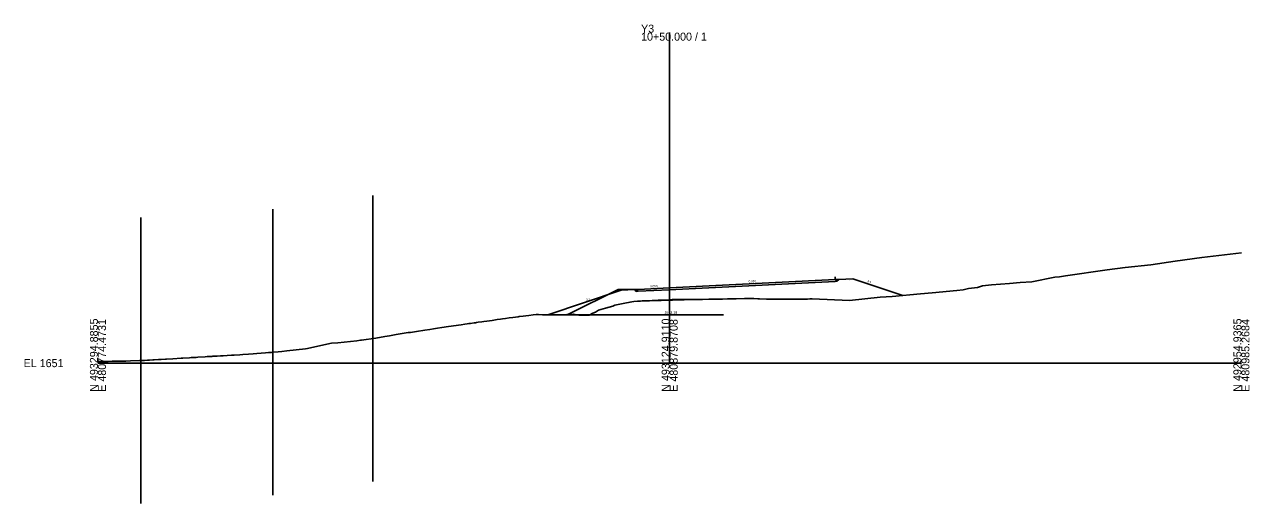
# Model space of a CAD drawing. Extents: x -26 to 481018, y -48 to 493233.
# Drawn here: x -25.7 to 402.8, y 450.9 to 618.4 of the extents above; entities that cross this region are included whole.
import ezdxf

# ---------------------------------------------------------------- set-up
doc = ezdxf.new("R2010")
doc.units = 0
for name, color, linetype in [('Exist Cross Section Cell', 7, 'Continuous'), ('Exist XS Center Line Elevation Label', 7, 'Continuous'), ('Exist XS Ground Line', 7, 'Continuous'), ('Prop XS Dump Level', 7, 'Continuous'), ('Prop XS Earthwork Shape', 7, 'Continuous'), ('Prop XS EOT Tick Mark', 7, 'Continuous'), ('Prop XS Finish Grade', 7, 'Continuous'), ('Prop XS Finish Grade Earthwork', 7, 'Continuous'), ('Prop XS Finish Grade Pavement', 7, 'Continuous'), ('Prop XS Pvmt Edge Slope', 7, 'Continuous'), ('Prop XS SE Text', 7, 'Continuous'), ('Prop XS Shoulder Borrow Shape', 7, 'Continuous'), ('Prop XS Side Slope Text', 7, 'Continuous'), ('Prop XS Subgrade Earthwork', 7, 'Continuous'), ('Scratch_Level_2', 7, 'Continuous'), ('Scratch_Level_4', 7, 'Continuous'), ('Scratch_Level_5', 7, 'Continuous')]:
    doc.layers.add(name, color=color, linetype=linetype)

msp = doc.modelspace()

# ---------------------------------------------------------------- linework, layer by layer
at = {"layer": 'Exist Cross Section Cell'}
for p, q in [((200, 500), (200, 615.55)), ((0, 500), (200, 500)), ((200, 500), (400, 500))]:
    msp.add_line(p, q, dxfattribs=at)
at = {"layer": 'Exist XS Ground Line'}
for p, q in [((376.79, 535.62), (386.19, 536.91)), ((386.19, 536.91), (400, 538.52)), ((338.48, 530.56), (353.09, 532.59)), ((353.09, 532.59), (359.3, 533.49)), ((359.3, 533.49), (368.34, 534.34)), ((368.34, 534.34), (376.79, 535.62)), ((309.46, 527.08), (312.54, 527.4)), ((312.54, 527.4), (318.83, 527.9)), ((318.83, 527.9), (322.57, 528.16)), ((322.57, 528.16), (326.64, 528.41)), ((326.64, 528.41), (334.78, 530.01)), ((334.78, 530.01), (336.43, 530.19)), ((336.43, 530.19), (338.48, 530.56)), ((262.92, 521.94), (273.67, 523.04)), ((273.67, 523.04), (277.85, 523.36)), ((277.85, 523.36), (287.78, 524.27)), ((287.78, 524.27), (291.83, 524.6)), ((291.83, 524.6), (300.49, 525.41)), ((300.49, 525.41), (302.66, 525.69)), ((302.66, 525.69), (304.51, 526.1)), ((304.51, 526.1), (307.67, 526.5)), ((307.67, 526.5), (309.46, 527.08)), ((174.04, 517.87), (175.15, 518.58)), ((175.15, 518.58), (177.51, 519.18)), ((177.51, 519.18), (180.09, 519.96)), ((180.09, 519.96), (180.83, 520.23)), ((180.83, 520.23), (184.3, 520.95)), ((184.3, 520.95), (186.14, 521.34)), ((186.14, 521.34), (186.75, 521.42)), ((186.75, 521.42), (187.5, 521.52)), ((187.5, 521.52), (188.8, 521.63)), ((188.8, 521.63), (189.83, 521.71)), ((189.83, 521.71), (190.39, 521.74)), ((190.39, 521.74), (190.87, 521.77)), ((190.87, 521.77), (192.37, 521.84)), ((192.37, 521.84), (193.84, 521.9)), ((193.84, 521.9), (194.73, 521.94)), ((194.73, 521.94), (195.99, 522)), ((195.99, 522), (196.77, 522.03)), ((196.77, 522.03), (200, 522.18)), ((200, 522.18), (200.84, 522.21)), ((200.84, 522.21), (201.8, 522.22)), ((201.8, 522.22), (202.64, 522.23)), ((202.64, 522.23), (204.2, 522.24)), ((204.2, 522.24), (205.57, 522.25)), ((205.57, 522.25), (207.79, 522.28)), ((207.79, 522.28), (208.5, 522.29)), ((208.5, 522.29), (208.94, 522.3)), ((208.94, 522.3), (210.5, 522.31)), ((210.5, 522.31), (211.45, 522.31)), ((211.45, 522.31), (213.7, 522.32)), ((213.7, 522.32), (214.38, 522.32)), ((214.38, 522.32), (215.93, 522.34)), ((215.93, 522.34), (217.32, 522.37)), ((217.32, 522.37), (218.45, 522.4)), ((218.45, 522.4), (220.27, 522.43)), ((220.27, 522.43), (221.38, 522.46)), ((221.38, 522.46), (223.3, 522.49)), ((223.3, 522.49), (226.16, 522.55)), ((226.16, 522.55), (227.68, 522.59)), ((227.68, 522.59), (228.34, 522.61)), ((228.34, 522.61), (229.48, 522.56)), ((229.48, 522.56), (230.84, 522.5)), ((230.84, 522.5), (231.48, 522.47)), ((231.48, 522.47), (233.91, 522.39)), ((233.91, 522.39), (237.31, 522.32)), ((237.31, 522.32), (240.03, 522.33)), ((240.03, 522.33), (240.74, 522.33)), ((240.74, 522.33), (242.73, 522.38)), ((242.73, 522.38), (246.97, 522.39)), ((246.97, 522.39), (248.2, 522.42)), ((248.2, 522.42), (249.09, 522.45)), ((249.09, 522.45), (249.88, 522.48)), ((249.88, 522.48), (262.92, 521.94)), ((132.43, 514.2), (133.05, 514.29)), ((133.05, 514.29), (134.32, 514.47)), ((134.32, 514.47), (134.99, 514.56)), ((134.99, 514.56), (136.06, 514.71)), ((136.06, 514.71), (137.92, 514.97)), ((137.92, 514.97), (139.69, 515.22)), ((139.69, 515.22), (140.86, 515.39)), ((140.86, 515.39), (141.5, 515.47)), ((141.5, 515.47), (142.55, 515.61)), ((142.55, 515.61), (143.81, 515.79)), ((143.81, 515.79), (145.13, 515.97)), ((145.13, 515.97), (146.95, 516.21)), ((146.95, 516.21), (147.31, 516.26)), ((147.31, 516.26), (148.77, 516.45)), ((148.77, 516.45), (149.67, 516.58)), ((149.67, 516.58), (150.75, 516.71)), ((150.75, 516.71), (152.21, 516.91)), ((152.21, 516.91), (153.33, 517.04)), ((153.33, 517.04), (154.11, 517.01)), ((154.11, 517.01), (155.57, 516.95)), ((155.57, 516.95), (159.84, 516.9)), ((159.84, 516.9), (163.98, 517.04)), ((163.98, 517.04), (166.39, 517.17)), ((166.39, 517.17), (168.28, 516.8)), ((168.28, 516.8), (169.84, 516.74)), ((169.84, 516.74), (171.79, 516.8)), ((171.79, 516.8), (173.08, 517.42)), ((173.08, 517.42), (174.04, 517.87)), ((101.98, 509.52), (104.29, 509.97)), ((104.29, 509.97), (105.71, 510.21)), ((105.71, 510.21), (106.46, 510.31)), ((106.46, 510.31), (108.52, 510.66)), ((108.52, 510.66), (109.32, 510.77)), ((109.32, 510.77), (111.46, 511.1)), ((111.46, 511.1), (114.41, 511.54)), ((114.41, 511.54), (116.1, 511.8)), ((116.1, 511.8), (117.35, 511.99)), ((117.35, 511.99), (118.8, 512.2)), ((118.8, 512.2), (120.28, 512.43)), ((120.28, 512.43), (122.65, 512.78)), ((122.65, 512.78), (123.56, 512.92)), ((123.56, 512.92), (126.14, 513.31)), ((126.14, 513.31), (127.05, 513.43)), ((127.05, 513.43), (128.3, 513.62)), ((128.3, 513.62), (129.11, 513.74)), ((129.11, 513.74), (129.8, 513.84)), ((129.8, 513.84), (130.37, 513.92)), ((130.37, 513.92), (131.59, 514.09)), ((131.59, 514.09), (132.05, 514.15)), ((132.05, 514.15), (132.43, 514.2)), ((73.75, 505.21), (81.74, 506.93)), ((81.74, 506.93), (83.87, 507.14)), ((83.87, 507.14), (90.53, 507.79)), ((90.53, 507.79), (91.83, 507.98)), ((91.83, 507.98), (92.24, 508.04)), ((92.24, 508.04), (97.2, 508.77)), ((97.2, 508.77), (100.38, 509.3)), ((100.38, 509.3), (101.98, 509.52)), ((22.13, 501.32), (23.59, 501.4)), ((23.59, 501.4), (24, 501.42)), ((24, 501.42), (26.14, 501.55)), ((26.14, 501.55), (29.09, 501.72)), ((29.09, 501.72), (29.66, 501.75)), ((29.66, 501.75), (32.03, 501.89)), ((32.03, 501.89), (32.58, 501.92)), ((32.58, 501.92), (33.47, 501.98)), ((33.47, 501.98), (34.39, 502.03)), ((34.39, 502.03), (34.97, 502.07)), ((34.97, 502.07), (37.48, 502.23)), ((37.48, 502.23), (38.17, 502.27)), ((38.17, 502.27), (38.6, 502.3)), ((38.6, 502.3), (39.55, 502.36)), ((39.55, 502.36), (39.86, 502.37)), ((39.86, 502.37), (40.24, 502.39)), ((40.24, 502.39), (41.68, 502.47)), ((41.68, 502.47), (42.89, 502.54)), ((42.89, 502.54), (43.79, 502.59)), ((43.79, 502.59), (45.26, 502.68)), ((45.26, 502.68), (46.74, 502.77)), ((46.74, 502.77), (47.08, 502.79)), ((47.08, 502.79), (47.63, 502.83)), ((47.63, 502.83), (49.68, 502.95)), ((49.68, 502.95), (50.71, 503.02)), ((50.71, 503.02), (52.63, 503.15)), ((52.63, 503.15), (54.34, 503.27)), ((54.34, 503.27), (55.57, 503.36)), ((55.57, 503.36), (57.13, 503.49)), ((57.13, 503.49), (58.58, 503.59)), ((58.58, 503.59), (59.63, 503.67)), ((59.63, 503.67), (60.66, 503.74)), ((60.66, 503.74), (61.38, 503.83)), ((61.38, 503.83), (63.1, 503.95)), ((63.1, 503.95), (64.34, 504.09)), ((64.34, 504.09), (66.11, 504.31)), ((66.11, 504.31), (72.62, 504.95)), ((72.62, 504.95), (73.28, 505.11)), ((73.28, 505.11), (73.75, 505.21)), ((0, 500.54), (2.61, 500.59)), ((2.61, 500.59), (3.53, 500.61)), ((3.53, 500.61), (4.99, 500.66)), ((4.99, 500.66), (5.56, 500.67)), ((5.56, 500.67), (7.16, 500.69)), ((7.16, 500.69), (8.49, 500.72)), ((8.49, 500.72), (9.76, 500.75)), ((9.76, 500.75), (11.43, 500.8)), ((11.43, 500.8), (14.48, 500.92)), ((14.48, 500.92), (16.23, 500.98)), ((16.23, 500.98), (17.31, 501.04)), ((17.31, 501.04), (18.05, 501.08)), ((18.05, 501.08), (19.23, 501.14)), ((19.23, 501.14), (19.66, 501.17)), ((19.66, 501.17), (21.19, 501.27)), ((21.19, 501.27), (22.13, 501.32))]:
    msp.add_line(p, q, dxfattribs=at)
at = {"layer": 'Prop XS Earthwork Shape'}
msp.add_lwpolyline([(257.94, 528.59), (258.53, 528.62), (259.19, 529.27), (264.06, 529.51), (281.51, 523.7), (277.85, 523.36), (273.67, 523.04), (262.92, 521.94), (249.88, 522.48), (249.09, 522.45), (248.2, 522.42), (246.97, 522.39), (242.73, 522.38), (240.74, 522.33), (240.03, 522.33), (237.31, 522.32), (233.91, 522.39), (231.48, 522.47), (230.84, 522.5), (229.48, 522.56), (228.34, 522.61), (227.68, 522.59), (226.16, 522.55), (223.3, 522.49), (221.38, 522.46), (220.27, 522.43), (218.45, 522.4), (217.32, 522.37), (215.93, 522.34), (214.38, 522.32), (213.7, 522.32), (211.45, 522.31), (210.5, 522.31), (208.94, 522.3), (208.5, 522.29), (207.79, 522.28), (205.57, 522.25), (204.2, 522.24), (202.64, 522.23), (201.8, 522.22), (200.84, 522.21), (200, 522.18), (196.77, 522.03), (195.99, 522), (194.73, 521.94), (193.84, 521.9), (192.37, 521.84), (190.87, 521.77), (190.39, 521.74), (189.83, 521.71), (188.8, 521.63), (187.5, 521.52), (186.75, 521.42), (186.14, 521.34), (184.3, 520.95), (180.83, 520.23), (180.09, 519.96), (177.51, 519.18), (175.15, 518.58), (174.04, 517.87), (173.08, 517.42), (171.79, 516.8), (169.84, 516.74), (168.28, 516.8), (166.39, 517.17), (163.98, 517.04), (159.84, 516.9), (157.41, 516.93), (183.01, 525.46), (187.75, 525.7), (188.34, 525.1), (189, 525.14), (200, 525.69), (209, 526.14)], close=True, dxfattribs=at)
at = {"layer": 'Prop XS EOT Tick Mark'}
msp.add_line((257.94, 529.21), (257.94, 530.21), dxfattribs=at)
at = {"layer": 'Prop XS Finish Grade'}
for p, q in [((257.94, 529.21), (259.19, 529.27)), ((189, 525.76), (187.75, 525.7))]:
    msp.add_line(p, q, dxfattribs=at)
at = {"layer": 'Prop XS Finish Grade Earthwork'}
for p, q in [((259.19, 529.27), (264.06, 529.51)), ((264.06, 529.51), (281.51, 523.7)), ((183.01, 525.46), (157.41, 516.93)), ((183.01, 525.46), (187.75, 525.7))]:
    msp.add_line(p, q, dxfattribs=at)
at = {"layer": 'Prop XS Finish Grade Pavement'}
for p, q in [((200, 526.31), (257.94, 529.21)), ((189, 525.76), (200, 526.31))]:
    msp.add_line(p, q, dxfattribs=at)
at = {"layer": 'Prop XS Pvmt Edge Slope'}
for p, q in [((257.94, 529.21), (258.53, 528.62)), ((189, 525.76), (188.34, 525.1))]:
    msp.add_line(p, q, dxfattribs=at)
at = {"layer": 'Prop XS Shoulder Borrow Shape'}
for points in [[(257.94, 529.21), (259.19, 529.27), (258.53, 528.62)], [(259.19, 529.27), (258.53, 528.62), (257.94, 529.21)], [(259.19, 529.27), (258.53, 528.62), (257.94, 529.21)], [(259.19, 529.27), (258.53, 528.62), (257.94, 529.21)], [(189, 525.76), (187.75, 525.7), (188.34, 525.1)], [(187.75, 525.7), (188.34, 525.1), (189, 525.76)], [(187.75, 525.7), (188.34, 525.1), (189, 525.76)], [(187.75, 525.7), (188.34, 525.1), (189, 525.76)]]:
    msp.add_lwpolyline(points, close=True, dxfattribs=at)
at = {"layer": 'Prop XS Subgrade Earthwork'}
for p, q in [((257.94, 528.59), (209, 526.14)), ((257.94, 528.59), (258.53, 528.62)), ((259.19, 529.27), (258.53, 528.62)), ((187.75, 525.7), (188.34, 525.1)), ((189, 525.14), (188.34, 525.1)), ((189, 525.14), (200, 525.69)), ((200, 525.69), (209, 526.14))]:
    msp.add_line(p, q, dxfattribs=at)
at = {"layer": 'Scratch_Level_2'}
for p, q in [((182, 525.76), (164.63, 517.07)), ((189, 525.76), (182, 525.76)), ((157.41, 516.93), (218.86, 516.93))]:
    msp.add_line(p, q, dxfattribs=at)
at = {"layer": 'Scratch_Level_4'}
msp.add_line((189, 521.65), (209, 522.3), dxfattribs=at)
at = {"layer": 'Scratch_Level_5'}
for p, q in [((96.22, 558.62), (96.22, 458.62)), ((96.22, 558.62), (96.22, 458.62)), ((61.14, 553.8), (61.14, 453.8)), ((15, 550.94), (15, 450.94))]:
    msp.add_line(p, q, dxfattribs=at)

# ---------------------------------------------------------------- texts
at = {"layer": 'Exist Cross Section Cell'}
for s, p in [('Y3', (190, 615.55)), ('10+50.000 / 1', (190, 612.75)), ('EL 1651', (-26, 498.6))]:
    msp.add_text(s, height=2.8, dxfattribs=at).set_placement(p)
for s, p in [('N 493294.8855', (0, 490)), ('E 480774.4731', (2.8, 490)), ('N 493124.9110', (200, 490)), ('E 480879.8708', (202.8, 490)), ('N 492954.9365', (400, 490)), ('E 480985.2684', (402.8, 490))]:
    msp.add_text(s, height=2.8, rotation=90, dxfattribs=at).set_placement(p)
at = {"layer": 'Exist XS Center Line Elevation Label'}
msp.add_text('1673.18', height=0.9, dxfattribs=at).set_placement((198.16, 517.28))
at = {"layer": 'Prop XS Dump Level'}
msp.add_text('Case2', height=0.04, rotation=5.153, dxfattribs=at).set_placement((262.94, 528.76))
msp.add_text('Case2', height=0.04, dxfattribs=at).set_placement((339.64, 528.31))
at = {"layer": 'Prop XS SE Text'}
for p in [(193.18, 526.47), (227.65, 528.19)]:
    msp.add_text('0.050', height=0.75, rotation=2.8624, dxfattribs=at).set_placement(p)
at = {"layer": 'Prop XS Side Slope Text'}
for rotation, p in [(341.5651, (269.05, 528.41)), (18.4349, (170.93, 521.71))]:
    msp.add_text('3:1', height=0.75, rotation=rotation, dxfattribs=at).set_placement(p)

doc.saveas('drawing.dxf')
